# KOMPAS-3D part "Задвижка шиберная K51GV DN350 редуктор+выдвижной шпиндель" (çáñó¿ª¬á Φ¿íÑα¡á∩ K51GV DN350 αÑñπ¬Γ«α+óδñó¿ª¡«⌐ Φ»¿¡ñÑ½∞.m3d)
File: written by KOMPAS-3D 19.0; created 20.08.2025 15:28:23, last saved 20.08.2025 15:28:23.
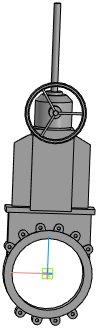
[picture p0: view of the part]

Document properties: Полное имя файла: Задвижка шиберная K51GV DN350 редуктор+выдвижной шпиндель.a3d

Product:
- Part/product: Задвижка шиберная K51GV DN350 редуктор+выдвижной шпиндель
    Масса: 115.862

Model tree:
1. Операция без истории:1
